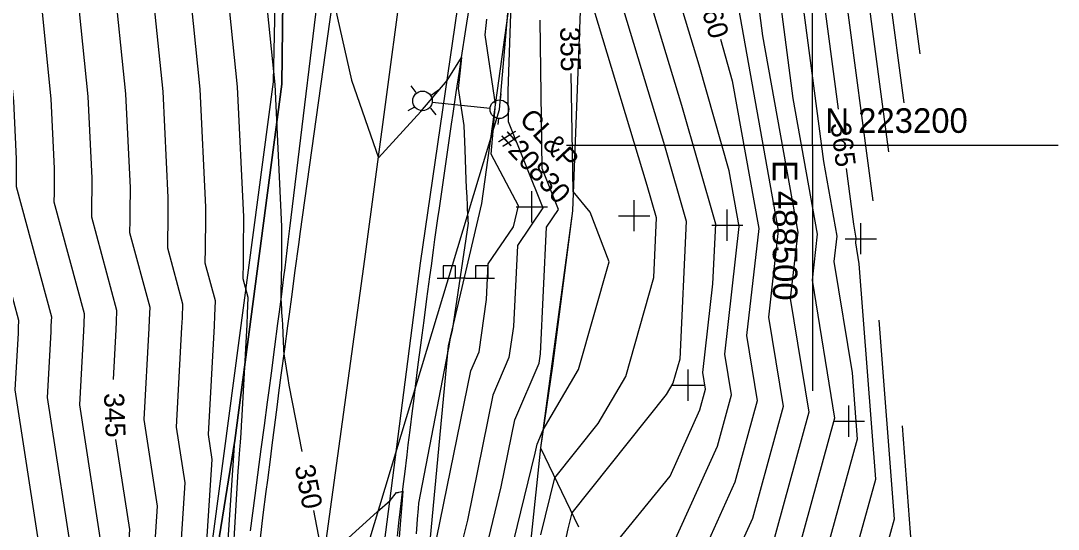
# Model space of a CAD drawing. Extents: x 487096 to 489566, y 221939 to 224454.
# Drawn here: x 488373.2 to 488539.4, y 223138.5 to 223219.9 of the extents above; entities that cross this region are included whole.
import ezdxf

# ---------------------------------------------------------------- set-up
doc = ezdxf.new("R2010")
doc.units = 0
for name, color, linetype in [('SV_BKLN_EARTH_TOP', 7, 'Continuous'), ('SV_FENC_FENCES', 7, 'Continuous'), ('SV_GRID_GRID', 7, 'Continuous'), ('SV_ROAD_BITRD', 7, 'Continuous'), ('SV_ROWL_HWYLOC', 7, 'Continuous'), ('SV_SIGN_SIGN', 7, 'Continuous'), ('SV_SURF_INDEX_CONTOUR', 7, 'Continuous'), ('SV_SURF_INTER_CONTOUR', 7, 'Continuous'), ('SV_SURF_SPOT', 7, 'Continuous'), ('SV_TRAF_PVMTL', 7, 'Continuous'), ('SV_TREE_TREEVEG', 7, 'Continuous'), ('SV_UTOH_OVERHEAD_LINES', 7, 'Continuous'), ('SV_UTOH_UPOLT', 7, 'Continuous'), ('SV_UTOH_UTOH_TX', 7, 'Continuous'), ('SV_WALL_STONE_WALL', 7, 'Continuous')]:
    doc.layers.add(name, color=color, linetype=linetype)

msp = doc.modelspace()

# ---------------------------------------------------------------- linework, layer by layer
at = {"layer": 'SV_BKLN_EARTH_TOP'}
for points in [[(488425.92, 222945.04), (488428.16, 222977.23), (488428.57, 223001.38), (488431.19, 223029.45), (488433.27, 223064.76), (488435.62, 223093.09), (488438.49, 223133.72), (488441.68, 223167.83), (488447.06, 223190.64), (488452, 223226.55)], [(488391.81, 222875.89), (488390.57, 222921.01), (488388.64, 223000.07), (488389.41, 223042.33), (488396.48, 223078.48), (488405.53, 223123.26), (488407.48, 223152.68)]]:
    msp.add_lwpolyline(points, dxfattribs=at)
at = {"layer": 'SV_FENC_FENCES'}
msp.add_lwpolyline([(488400.56, 222861.83), (488391.82, 222875.91), (488387.65, 222918.23), (488386.77, 222964.1), (488384.51, 222999.56), (488389.41, 223042.33), (488396.48, 223078.48), (488402.8, 223123.48), (488407.48, 223152.68), (488415.01, 223209.78), (488415.39, 223241.14)], dxfattribs=at)
at = {"layer": 'SV_GRID_GRID'}
for p, q in [((488500, 223200), (488500, 223239.37)), ((488460.63, 223200), (488500, 223200)), ((488500, 223200), (488539.37, 223200)), ((488500, 223200), (488500, 223160.63))]:
    msp.add_line(p, q, dxfattribs=at)
at = {"layer": 'SV_ROAD_BITRD'}
for points in [[(488421.94, 223233.77), (488416.24, 223186.63), (488415.99, 223184.53), (488415.81, 223183.12), (488415.47, 223180.32), (488415.29, 223178.91), (488414.94, 223176.1), (488414.58, 223173.3), (488414.34, 223171.43), (488413.85, 223167.69), (488413.29, 223163.48), (488412.92, 223160.67), (488412.67, 223158.8), (488412.17, 223155.06), (488411.67, 223151.32), (488411.33, 223148.83), (488410.66, 223143.85), (488409.91, 223138.24)], [(488421.94, 223233.77), (488416.24, 223186.63), (488415.99, 223184.53), (488415.81, 223183.12), (488415.47, 223180.32), (488415.29, 223178.91), (488414.94, 223176.1), (488414.58, 223173.3), (488414.34, 223171.43), (488413.85, 223167.69), (488413.29, 223163.48), (488412.92, 223160.67), (488412.67, 223158.8), (488412.17, 223155.06), (488411.67, 223151.32), (488411.33, 223148.83), (488410.66, 223143.85), (488409.91, 223138.24)], [(488421.94, 223233.77), (488416.24, 223186.63), (488415.99, 223184.53), (488415.81, 223183.12), (488415.47, 223180.32), (488415.29, 223178.91), (488414.94, 223176.1), (488414.58, 223173.3), (488414.34, 223171.43), (488413.85, 223167.69), (488413.29, 223163.48), (488412.92, 223160.67), (488412.67, 223158.8), (488412.17, 223155.06), (488411.67, 223151.32), (488411.33, 223148.83), (488410.66, 223143.85), (488409.91, 223138.24)], [(488433.52, 223137.38), (488433.77, 223139.47), (488434.13, 223142.59), (488434.5, 223145.72), (488434.69, 223147.28), (488435.07, 223150.41), (488435.26, 223151.97), (488435.55, 223154.32), (488435.93, 223157.44), (488436.13, 223159), (488436.42, 223161.34), (488436.87, 223164.86), (488437.27, 223167.98), (488437.47, 223169.54), (488437.78, 223171.88), (488438.25, 223175.39), (488438.72, 223178.9), (488438.96, 223180.66), (488439.31, 223183.18), (488439.54, 223184.87), (488440.01, 223188.23), (488440.25, 223189.91), (488440.73, 223193.28), (488441.22, 223196.64), (488441.54, 223198.89), (488442.2, 223203.37), (488442.45, 223205.05), (488442.95, 223208.41), (488443.46, 223211.78), (488443.79, 223214.02), (488444.48, 223218.5), (488444.99, 223221.86)]]:
    msp.add_lwpolyline(points, dxfattribs=at)
at = {"layer": 'SV_ROWL_HWYLOC'}
for points in [[(488415.39, 223241.14), (488415.01, 223209.78), (488407.48, 223152.68), (488402.8, 223123.48), (488396.48, 223078.48), (488389.41, 223042.33), (488386.96, 223020.94), (488384.51, 222999.56), (488386.77, 222964.1), (488387.65, 222918.23), (488391.82, 222875.91), (488394, 222859.24), (488415.21, 222774.39)], [(488463.17, 223231.25), (488461.58, 223189.46), (488456.44, 223151.49), (488440.47, 223000.12), (488440.59, 222898.56), (488442.96, 222863.75), (488470.32, 222775.78)]]:
    msp.add_lwpolyline(points, dxfattribs=at)
at = {"layer": 'SV_SIGN_SIGN'}
for p, q in [((488439.88, 223178.69), (488440.85, 223178.69)), ((488444.44, 223178.7), (488442.83, 223178.7)), ((488444.44, 223178.7), (488446.04, 223178.7)), ((488444.44, 223178.7), (488446.04, 223178.7)), ((488448.03, 223178.69), (488449.06, 223178.69))]:
    msp.add_line(p, q, dxfattribs=at)
for points in [[(488440.83, 223178.7), (488442.83, 223178.7), (488442.83, 223180.67), (488440.83, 223180.67)], [(488446.04, 223178.7), (488448.04, 223178.7), (488448.04, 223180.67), (488446.04, 223180.67)]]:
    msp.add_lwpolyline(points, close=True, dxfattribs=at)
at = {"layer": 'SV_SURF_INDEX_CONTOUR'}
for points in [[(488504.19, 223205.76), (488501.58, 223225.52), (488503.75, 223250.45), (488504.35, 223263.58), (488510.85, 223282.86), (488511.4, 223284.79), (488512.19, 223290.68)], [(488388.03, 223162.47), (488388.47, 223170.46), (488388.52, 223171.69), (488388.6, 223173.52), (488384.55, 223188.46), (488384.58, 223190.14), (488384.6, 223190.97), (488384.61, 223192.64), (488384.62, 223193.46), (488384.62, 223194.7), (488384, 223207.81), (488382.28, 223224.63), (488369.93, 223244.67)], [(488411.12, 223236.77), (488413.89, 223209.71), (488414.98, 223186.96), (488414.97, 223184.82), (488414.96, 223183.38), (488414.93, 223180.5), (488414.91, 223179.05), (488414.86, 223176.14), (488414.87, 223176.1), (488414.84, 223175.35), (488414.95, 223173.76), (488414.98, 223173.2), (488415.06, 223172.01), (488415.1, 223171.25), (488415.17, 223169.84), (488415.28, 223167.35), (488415.29, 223167.1), (488415.31, 223166.55), (488415.7, 223164.29), (488415.96, 223162.61), (488416.11, 223161.55), (488418.21, 223150.91)], [(488485.26, 223216.96), (488487.16, 223210.28), (488491.39, 223186.66), (488489.45, 223169.49), (488491.16, 223159.05), (488487.57, 223146), (488481.8, 223133.21)], [(488450.65, 223129.64), (488452.16, 223136.66), (488455.59, 223150.64), (488455.88, 223152.1), (488456.86, 223154.4), (488462.53, 223164.04), (488467.43, 223181.31), (488464.39, 223189.24), (488461.69, 223192.55), (488461.33, 223211.48)], [(488499.53, 223111.71), (488501.1, 223116.22), (488503.87, 223123.79), (488510.13, 223146.5), (488507.48, 223180.99), (488506.94, 223184.33), (488507.02, 223185.09), (488506.62, 223187.33), (488505.44, 223196.24)], [(488378.59, 223068.14), (488379, 223079.61), (488379.79, 223087.96), (488382.88, 223098.56), (488389.58, 223121.96), (488390.65, 223138.41), (488388.42, 223152.87)], [(488420.06, 223141.49), (488421.65, 223133.41), (488430.28, 223141.25), (488432.34, 223143.08), (488433.39, 223144.34), (488433.52, 223144.36), (488433.64, 223144.38), (488433.75, 223144.41), (488434.02, 223144.48), (488434.21, 223144.54), (488434.37, 223144.59), (488434.21, 223142.45), (488433.96, 223139.23), (488433.81, 223137.17), (488433.52, 223133.26), (488433.23, 223129.06), (488432.84, 223125.71), (488429.93, 223086.05), (488429.82, 223083.83), (488429.81, 223083.68)]]:
    msp.add_lwpolyline(points, dxfattribs=at)
at = {"layer": 'SV_SURF_INTER_CONTOUR'}
for points in [[(488510.21, 223481.15), (488508.79, 223451.48), (488511.61, 223434.9), (488518.66, 223429.65), (488525.5, 223402.41), (488527.36, 223389.85), (488527.77, 223380.2), (488523.16, 223363.19), (488510.47, 223341.61), (488517.98, 223319.59), (488518.89, 223315.4), (488517.58, 223306.28), (488514.66, 223284.35), (488513.56, 223280.5), (488507.71, 223263.16), (488506.9, 223245.48), (488505.15, 223225.3), (488509.67, 223191.06)], [(488512.54, 223478.52), (488511.24, 223451.22), (488513.83, 223435.97), (488520.32, 223431.14), (488528.49, 223398.58), (488529.76, 223390.02), (488530.23, 223378.81), (488524.88, 223359.04), (488514, 223340.55), (488522.2, 223316.5), (488522.24, 223316.4), (488522.22, 223316.27), (488517.92, 223283.9), (488516.27, 223278.14), (488511.07, 223262.74), (488510.06, 223240.5), (488508.72, 223225.09), (488512.17, 223198.92)], [(488514.68, 223206.77), (488512.29, 223224.87), (488513.21, 223235.53), (488514.44, 223262.32), (488518.98, 223275.78), (488521.17, 223283.46), (488524.95, 223311.87), (488525.38, 223316), (488524.37, 223319.45), (488517.53, 223339.49), (488526.6, 223354.9), (488532.69, 223377.42), (488532.16, 223390.19), (488531.48, 223394.75), (488521.97, 223432.64), (488516.05, 223437.04), (488513.68, 223450.96), (488514.87, 223475.88)], [(488517.21, 223473.25), (488516.13, 223450.71), (488518.27, 223438.11), (488523.63, 223434.13), (488534.47, 223390.92), (488534.56, 223390.36), (488535.16, 223376.03), (488528.32, 223350.76), (488521.06, 223338.43), (488526.53, 223322.39), (488528.52, 223315.61), (488527.68, 223307.47), (488524.43, 223283.01), (488521.69, 223273.42), (488517.8, 223261.9), (488516.37, 223230.56), (488515.86, 223224.65), (488517.18, 223214.63)], [(488359.77, 223236.87), (488370.82, 223218.92), (488372.04, 223207.04), (488372.48, 223197.79), (488372.48, 223196.92), (488372.48, 223196.34), (488372.46, 223195.16), (488372.45, 223194.58), (488372.43, 223193.39), (488378.09, 223172.49), (488378.03, 223171.04), (488377.99, 223170.07), (488377.41, 223159.59), (488381.85, 223130.93), (488381.2, 223120.99), (488374.29, 223096.91), (488372.27, 223089.95), (488373, 223083.2), (488371.57, 223043.15), (488372.28, 223018.17), (488372.2, 223002.18), (488372.91, 222974.28)], [(488406.76, 223126.83), (488408, 223147.77), (488408.1, 223148.95), (488408.24, 223150.56), (488408.34, 223151.81), (488408.38, 223152.38), (488408.44, 223153.17), (488408.49, 223153.87), (488408.51, 223154.19), (488408.53, 223154.64), (488408.57, 223155.25), (488408.59, 223155.72), (488409.44, 223171.24), (488409.51, 223172.99), (488409.61, 223175.58), (488408.8, 223178.6), (488408.85, 223181.27), (488408.87, 223182.59), (488408.89, 223185.23), (488408.9, 223186.55), (488408.91, 223188.5), (488407.91, 223209.33), (488405.18, 223236.05)], [(488402.16, 223123.41), (488403.87, 223149.62), (488403.24, 223153.65), (488404.2, 223171.05), (488404.27, 223172.66), (488404.36, 223175.07), (488402.74, 223181.07), (488402.78, 223183.49), (488402.8, 223184.69), (488402.82, 223187.08), (488402.83, 223188.27), (488402.84, 223190.05), (488401.94, 223208.95), (488399.45, 223233.2)], [(488356.35, 223230.28), (488365.1, 223216.06), (488366.06, 223206.66), (488366.41, 223199.34), (488366.41, 223198.65), (488366.41, 223198.19), (488366.4, 223197.26), (488366.39, 223196.79), (488366.37, 223195.86), (488372.83, 223171.98), (488372.78, 223170.72), (488372.75, 223169.88), (488372.25, 223160.78), (488377.44, 223127.2), (488377.01, 223120.51), (488372.36, 223104.31), (488368.14, 223089.82), (488369.68, 223075.78), (488368.51, 223043.29), (488369.09, 223023.02), (488368.99, 223002.86), (488369.65, 222976.67)], [(488393.73, 223230.34), (488395.96, 223208.57), (488396.77, 223191.6), (488396.76, 223190), (488396.75, 223188.93), (488396.73, 223186.78), (488396.72, 223185.7), (488396.68, 223183.53), (488399.1, 223174.55), (488399.02, 223172.34), (488398.96, 223170.85), (488398.08, 223154.84), (488399.46, 223145.88), (488397.97, 223122.92), (488395.52, 223114.37), (488386.68, 223084.05), (488384.42, 223060.17), (488383.8, 223042.58), (488384.92, 223003.12), (488385.18, 222999.65), (488385.4, 222985.63), (488385.93, 222964.71)], [(488467.07, 223230.47), (488476.31, 223199.95), (488479.77, 223187.84), (488478.75, 223165.72), (488477.66, 223161.88), (488476.59, 223160.05), (488461.46, 223141.08), (488460.84, 223138.52), (488458.65, 223128.33)], [(488460.59, 222976.59), (488459.96, 222983.42), (488460.3, 223000.75), (488459.44, 223004.49), (488459.56, 223013.69), (488458.96, 223027.39), (488459.08, 223040.67), (488461.24, 223054.03), (488462.88, 223064.68), (488465.32, 223078.41), (488466.33, 223083.84), (488467.88, 223098.6), (488467.74, 223098.81), (488471.57, 223109.93), (488474.24, 223128.46), (488484.78, 223151.79), (488487.02, 223159.98), (488485.96, 223166.52), (488488.26, 223186.97), (488486.67, 223195.9), (488481.85, 223212.78), (488477.1, 223228.48)], [(488467.1, 223134.6), (488477.19, 223146.97), (488481.98, 223157.59), (488482.89, 223160.9), (488482.46, 223163.55), (488484.06, 223177.78), (488484.5, 223187.36), (488479.08, 223206.36), (488472.09, 223229.47)], [(488388, 223227.49), (488389.98, 223208.19), (488390.7, 223193.15), (488390.69, 223191.73), (488390.68, 223190.79), (488390.66, 223188.88), (488390.65, 223187.92), (488390.61, 223186), (488393.85, 223174.04), (488393.77, 223172.01), (488393.71, 223170.66), (488392.91, 223156.03), (488395.06, 223142.14), (488393.78, 223122.44), (488389.2, 223106.46), (488383.23, 223086), (488381.71, 223069.89), (488380.74, 223042.72), (488381.85, 223003.61), (488381.84, 223000.13), (488382.68, 222967.11)], [(488490.87, 223226.17), (488492.01, 223217.49), (488497.64, 223186.03), (488496.45, 223175.43), (488499.42, 223157.2), (488493.16, 223134.4), (488489.43, 223126.13), (488488.48, 223119.56), (488478.42, 223090.31), (488478.79, 223089.77), (488478.09, 223083.14), (488475.18, 223067.52), (488473.96, 223062.13), (488468.8, 223029.45), (488468.76, 223029.1), (488468.75, 223028.74), (488470.07, 223000.06), (488469.75, 222982.34), (488470.16, 222976.6)], [(488494.44, 223225.95), (488496.88, 223207.44), (488500.77, 223185.72), (488499.94, 223178.39), (488503.55, 223156.28), (488495.96, 223128.6), (488494.49, 223125.35), (488494.12, 223122.77), (488481.98, 223087.48), (488482.42, 223086.82), (488482.01, 223082.9), (488480.29, 223073.67), (488477.6, 223061.78), (488473.51, 223035.88), (488472.67, 223029.09), (488472.4, 223022.19), (488473.43, 222999.92), (488473.18, 222986.17), (488473.88, 222976.3)], [(488498.01, 223225.74), (488501.75, 223197.38), (488503.89, 223185.4), (488503.44, 223181.36), (488506.35, 223163.5), (488507.16, 223152.92), (488499.36, 223124.57), (488498.63, 223122.6), (488494.54, 223110.82), (488485.54, 223084.65), (488486.06, 223083.88), (488485.93, 223082.67), (488485.4, 223079.82), (488481.23, 223061.42), (488478.22, 223042.31), (488476.58, 223029.07), (488476.05, 223015.65), (488476.78, 222999.79), (488476.61, 222990), (488477.6, 222975.99)], [(488423.18, 223223.68), (488426.18, 223210.38), (488430.47, 223197.98), (488437.29, 223205.4), (488441.48, 223210.34), (488443.8, 223214.02), (488443.8, 223214.02), (488443.58, 223211.99), (488443.27, 223209.06), (488444.17, 223203.13), (488444.31, 223199.22), (488444.37, 223197.68), (488444.5, 223194.46), (488444.55, 223193.21), (488444.62, 223191.66), (488444.68, 223190.39), (488444.71, 223189.84), (488444.76, 223188.87), (488444.78, 223188.45), (488444.81, 223187.87), (488444.84, 223187.51), (488442.27, 223170.32), (488441.93, 223168.82), (488441.78, 223167.81), (488441.76, 223167.74), (488441.6, 223166.97), (488436.91, 223142.64), (488436.84, 223141.77), (488436.71, 223140.09), (488436.64, 223139.28), (488436.52, 223137.73)], [(488451.76, 223224.18), (488451.2, 223208.62), (488451.26, 223203.8), (488456.8, 223189.93), (488452.73, 223183.91), (488452.12, 223170.93), (488451.39, 223165.97), (488448.82, 223159.92), (488444.74, 223139.91), (488443.49, 223134.8)], [(488487.66, 223224.66), (488494.52, 223186.34), (488492.95, 223172.46), (488495.29, 223158.13), (488490.37, 223140.2), (488484.36, 223126.91), (488482.84, 223116.35), (488474.86, 223093.15), (488475.15, 223092.71), (488474.17, 223083.37), (488470.51, 223063.69), (488470.31, 223062.6), (488470.18, 223061.76), (488465.51, 223032.81), (488465.47, 223028.55), (488466.57, 223003.23), (488466.71, 223000.19), (488466.33, 222978.51)], [(488376.55, 223221.78), (488378.02, 223207.43), (488378.55, 223196.24), (488378.55, 223195.19), (488378.55, 223194.49), (488378.53, 223193.07), (488378.52, 223192.36), (488378.49, 223190.93), (488383.34, 223173.01), (488383.28, 223171.37), (488383.23, 223170.27), (488382.58, 223158.4), (488386.25, 223134.67), (488385.39, 223121.48), (488376.55, 223090.65), (488376.34, 223089.91), (488376.28, 223089.33), (488374.63, 223043.01), (488375.47, 223013.32), (488375.41, 223001.5), (488376.16, 222971.89)], [(488456.5, 223137.59), (488458.74, 223146.73), (488465.65, 223155.4), (488470.1, 223162.96), (488474.59, 223178.81), (488475.03, 223188.33), (488473.54, 223193.53), (488465.04, 223221.63)], [(488439.31, 223134.54), (488445.29, 223163.83), (488446.59, 223166.89), (488447.81, 223175.28), (488448.08, 223180.99), (488452.09, 223186.93), (488452.89, 223190.25), (488448.53, 223198.55), (488449.25, 223206.56), (488447.57, 223217.66), (488447.72, 223219.15), (488447.83, 223220.18)], [(488447.82, 223135.73), (488450.16, 223145.28), (488452.35, 223156.01), (488456.2, 223165.05), (488456.42, 223166.58), (488457.38, 223186.83), (488459.31, 223189.68), (488456.68, 223196.26), (488456.4, 223220)], [(488510.64, 223171.96), (488513.09, 223140.07), (488508.39, 223123), (488503.56, 223109.84), (488494.75, 223084.48), (488490.15, 223069.04), (488490.17, 223068.06), (488488.5, 223060.72), (488487.63, 223055.17), (488484.4, 223029.05), (488483.36, 223002.55), (488483.5, 222999.53), (488483.46, 222997.66), (488484.37, 222984.74), (488485.32, 222977.61), (488485.61, 222971.74), (488490.22, 222949.53), (488492.94, 222942.82), (488498.08, 222925.42), (488502.36, 222905.59)], [(488501, 222923.81), (488500.59, 222925.71), (488494.49, 222946.4), (488493.29, 222949.36), (488491.25, 222959.16), (488490.02, 222984.81), (488487.77, 223001.68), (488487.6, 223011.01), (488488.31, 223029.03), (488491.49, 223054.73), (488492.39, 223060.38), (488492.98, 223062.58), (488499.92, 223085.9), (488506.02, 223103.45), (488512.9, 223122.22), (488516.05, 223133.65), (488514.41, 223155.01)]]:
    msp.add_lwpolyline(points, dxfattribs=at)
at = {"layer": 'SV_SURF_SPOT'}
for p, q in [((488455.05, 223187.6), (488455.05, 223192.61)), ((488452.55, 223190.11), (488457.55, 223190.11)), ((488455.05, 223190.11), (488455.05, 223190.11)), ((488471.45, 223186.19), (488471.45, 223191.19)), ((488468.95, 223188.69), (488473.96, 223188.69)), ((488471.45, 223188.69), (488471.45, 223188.69)), ((488486.36, 223184.66), (488486.36, 223189.67)), ((488483.86, 223187.17), (488488.87, 223187.17)), ((488486.36, 223187.17), (488486.36, 223187.17)), ((488507.74, 223182.51), (488507.74, 223187.51)), ((488505.24, 223185.01), (488510.24, 223185.01)), ((488507.74, 223185.01), (488507.74, 223185.01)), ((488480.08, 223159.03), (488480.08, 223164.03)), ((488477.58, 223161.53), (488482.59, 223161.53)), ((488480.08, 223161.53), (488480.08, 223161.53)), ((488505.85, 223153.26), (488505.85, 223158.27)), ((488503.35, 223155.76), (488508.35, 223155.76)), ((488505.85, 223155.76), (488505.85, 223155.76))]:
    msp.add_line(p, q, dxfattribs=at)
at = {"layer": 'SV_TRAF_PVMTL'}
for points in [[(488421.5, 223132.34), (488428.31, 223181.75), (488437.42, 223250.14)], [(488430.78, 223130.93), (488437.22, 223181.07), (488447.15, 223249.31)], [(488424.5, 223233.13), (488417.97, 223186.18), (488417.68, 223184.09), (488417.11, 223179.9), (488416.54, 223175.71), (488416.16, 223172.91), (488415.91, 223171.05), (488415.41, 223167.32), (488414.86, 223163.13), (488414.5, 223160.34), (488414.25, 223158.47), (488413.77, 223154.74), (488413.41, 223151.95), (488413.17, 223150.08), (488412.7, 223146.35), (488412.46, 223144.49), (488411.99, 223140.76), (488411.52, 223137.03)]]:
    msp.add_lwpolyline(points, dxfattribs=at)
at = {"layer": 'SV_TREE_TREEVEG'}
msp.add_lwpolyline([(488469.57, 222626.73), (488414.36, 222775.8), (488391.31, 222875.65), (488384.76, 223013.78), (488396.28, 223079.01), (488413.65, 223210.14), (488414.48, 223247.55), (488427.96, 223341.62), (488424.88, 223443.61), (488411.44, 223499.76), (488395.39, 223528.76), (488373.34, 223524.5)], dxfattribs=at)
at = {"layer": 'SV_UTOH_OVERHEAD_LINES'}
msp.add_lwpolyline([(488477.01, 222631.44), (488424.13, 222778.25), (488391.68, 223012.96), (488449.87, 223205.72), (488470, 223438.33), (488349.56, 223622.89), (488159.18, 223693.12), (487993.17, 223755.78), (487804.2, 223830.22), (487742.26, 223860.21)], dxfattribs=at)
at = {"layer": 'SV_UTOH_UPOLT'}
for p, q in [((488436.54, 223208.42), (488435.74, 223209.5)), ((488438.95, 223207.99), (488440.08, 223208.83)), ((488450.1, 223208.23), (488450, 223207.24)), ((488448.36, 223205.87), (488439.09, 223206.83)), ((488436.26, 223206.09), (488435.2, 223205.47)), ((488438.8, 223205.94), (488439.7, 223204.84)), ((488449.71, 223204.28), (488449.6, 223203.28))]:
    msp.add_line(p, q, dxfattribs=at)
for centre, radius in [((488437.54, 223207.08), 1.57), ((488449.86, 223205.75), 1.5)]:
    msp.add_circle(centre, radius, dxfattribs=at)
at = {"layer": 'SV_WALL_STONE_WALL'}
msp.add_lwpolyline([(488463.17, 223231.25), (488461.58, 223189.46), (488458.34, 223164.64), (488456.44, 223151.49), (488462.52, 223138.88)], dxfattribs=at)

# ---------------------------------------------------------------- texts
at = {"layer": 'SV_GRID_GRID'}
msp.add_text('N 223200', height=3.937, dxfattribs=at).set_placement((488502.05, 223201.96))
msp.add_text('E 488500', height=3.937, rotation=270, dxfattribs=at).set_placement((488493.65, 223197.64))
at = {"layer": 'SV_SURF_INDEX_CONTOUR'}
for s, rotation, p in [('360', 286.6183, (488481.59, 223223.64)), ('355', 271.1077, (488459.58, 223218.9)), ('365', 277.5228, (488502.88, 223203.42)), ('345', 272.2869, (488386.52, 223160.25)), ('350', 281.1259, (488417.05, 223148.5))]:
    msp.add_text(s, height=3.2, rotation=rotation, dxfattribs=at).set_placement(p)
at = {"layer": 'SV_UTOH_UTOH_TX'}
for s, p in [('CL&P', (488452.89, 223203.99)), ('#20830', (488449.45, 223200.79))]:
    msp.add_text(s, height=3.2, rotation=313.0386, dxfattribs=at).set_placement(p)

doc.saveas('drawing.dxf')
